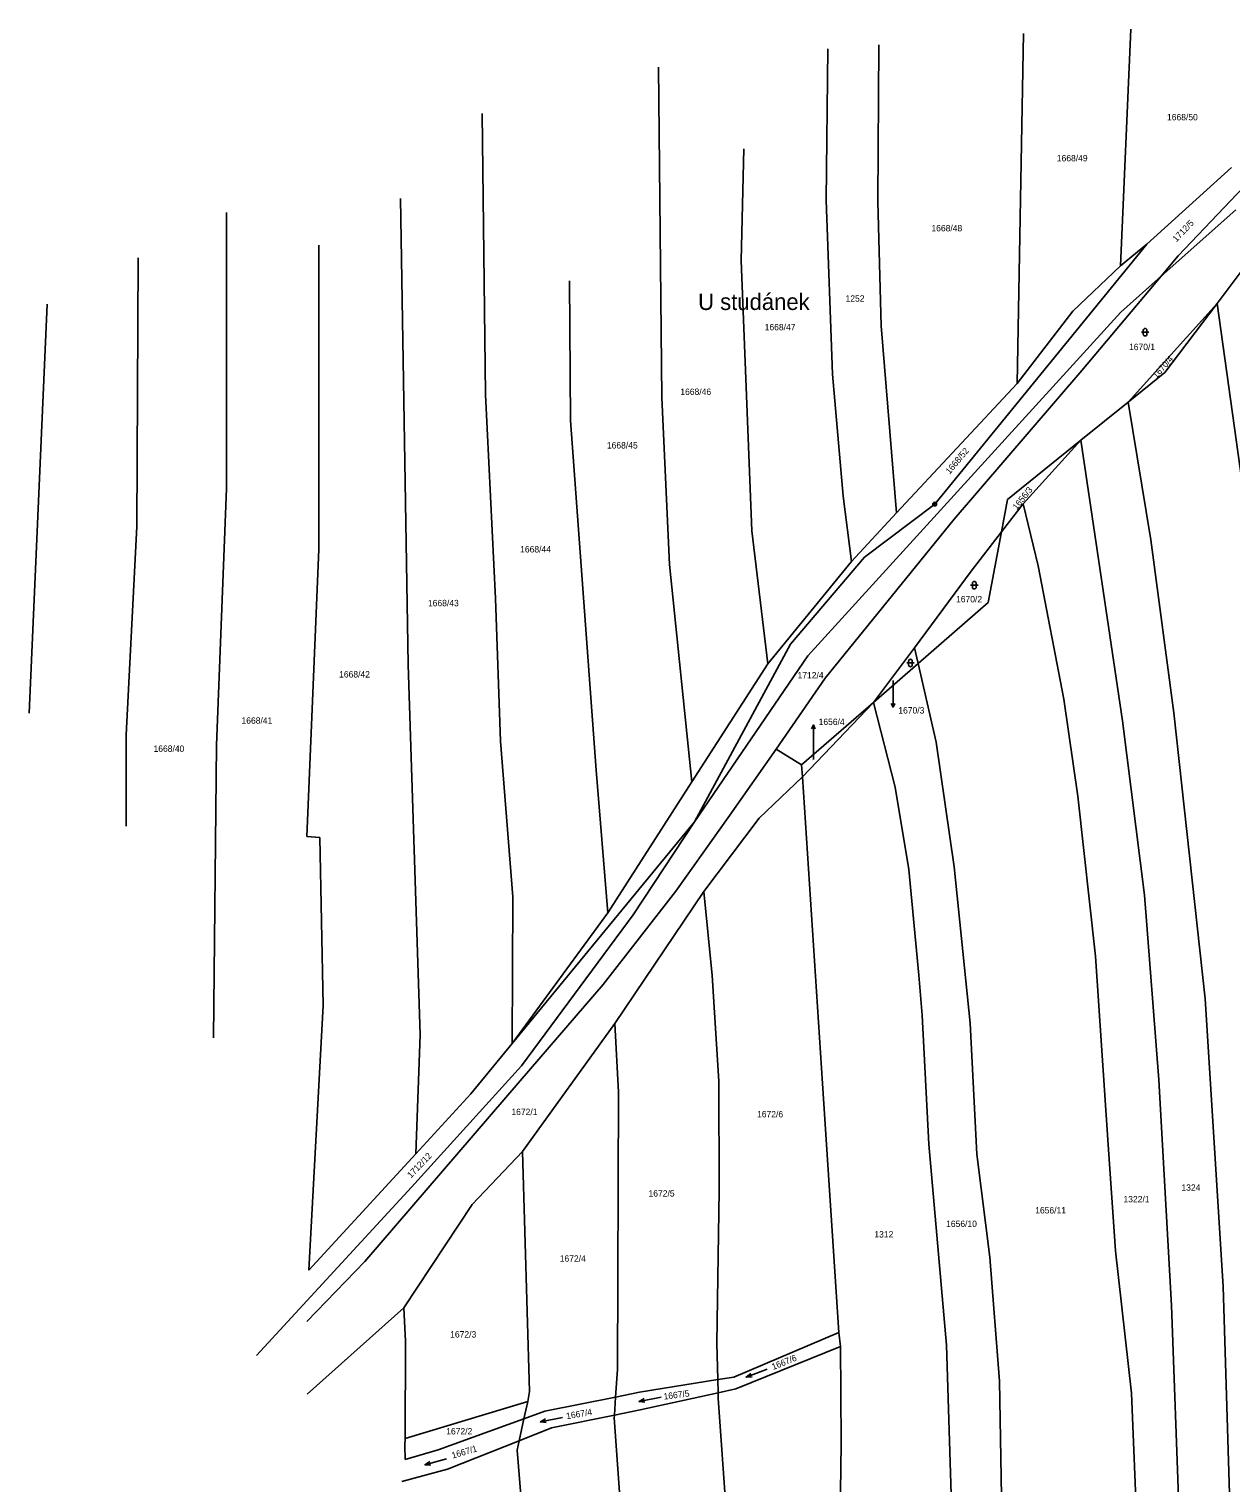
# Model space of a CAD drawing. Extents: x -763296 to -761805, y -1153670 to -1152034.
# Drawn here: x -763295.5 to -762975, y -1152752.7 to -1152364.9 of the extents above; entities that cross this region are included whole.
import ezdxf

# ---------------------------------------------------------------- set-up
doc = ezdxf.new("R2010")
doc.units = 0
for name, color, linetype in [('Vrstva 1', 7, 'Continuous'), ('Vrstva 15', 7, 'Continuous'), ('Vrstva 16', 7, 'Continuous'), ('Vrstva 18', 7, 'Continuous'), ('Vrstva 24', 7, 'Continuous'), ('Vrstva 25', 7, 'Continuous'), ('Vrstva 6', 7, 'Continuous')]:
    doc.layers.add(name, color=color, linetype=linetype)

msp = doc.modelspace()

# ---------------------------------------------------------------- linework, layer by layer
at = {"layer": 'Vrstva 1'}
for p, q in [((-762989.06, -1152425.44), (-762962.59, -1152397.59)), ((-762974.84, -1152401.85), (-762997.4, -1152422.3)), ((-762997.4, -1152422.3), (-763053.99, -1152491.63)), ((-762978.68, -1152438.1), (-762968.78, -1152424.96)), ((-762993.56, -1152430.81), (-762989.06, -1152425.44)), ((-763014.7, -1152456.04), (-762993.56, -1152430.81)), ((-762992.57, -1152456.53), (-762978.68, -1152438.1)), ((-763048.79, -1152495.66), (-763014.7, -1152456.04)), ((-763002.38, -1152464.44), (-762992.57, -1152456.53)), ((-763015, -1152474.6), (-763002.38, -1152464.44)), ((-763034.6, -1152490.4), (-763015, -1152474.6)), ((-763036.21, -1152499.07), (-763034.6, -1152490.4)), ((-763053.99, -1152491.63), (-763072.74, -1152505.77)), ((-763083.23, -1152538.1), (-763048.79, -1152495.66)), ((-763039.69, -1152517.84), (-763036.21, -1152499.07)), ((-763072.74, -1152505.77), (-763092.4, -1152529.01)), ((-763058.42, -1152534.15), (-763039.69, -1152517.84)), ((-763092.4, -1152529.01), (-763118.09, -1152576.34)), ((-763070.34, -1152544.53), (-763058.42, -1152534.15)), ((-763096.23, -1152556.97), (-763083.23, -1152538.1)), ((-763089.48, -1152561.2), (-763070.34, -1152544.53)), ((-763108.59, -1152574.57), (-763096.23, -1152556.97)), ((-763096.23, -1152556.97), (-763089.48, -1152561.2)), ((-763089.48, -1152561.2), (-763089.27, -1152564.37)), ((-763089.27, -1152564.37), (-763083.91, -1152646.15)), ((-763118.09, -1152576.34), (-763166.68, -1152635.49)), ((-763123, -1152594.92), (-763108.59, -1152574.57)), ((-763142.38, -1152619.81), (-763123, -1152594.92)), ((-763164.58, -1152645.44), (-763142.38, -1152619.81)), ((-763166.68, -1152635.49), (-763177.74, -1152648.96)), ((-763206.02, -1152693.64), (-763164.58, -1152645.44)), ((-763083.91, -1152646.15), (-763079.55, -1152712.57)), ((-763177.74, -1152648.96), (-763192.41, -1152664.95)), ((-763192.41, -1152664.95), (-763220.87, -1152695.98)), ((-763221.49, -1152709.63), (-763206.02, -1152693.64)), ((-763107.58, -1152724.48), (-763079.55, -1152712.57)), ((-763079.55, -1152712.57), (-763079.07, -1152716.28)), ((-763079.07, -1152716.28), (-763107.05, -1152727.6)), ((-763132.7, -1152728.51), (-763111.84, -1152725.16)), ((-763111.84, -1152725.16), (-763107.58, -1152724.48)), ((-763107.05, -1152727.6), (-763111.76, -1152728.64)), ((-763157.95, -1152733.58), (-763139.1, -1152729.8)), ((-763139.1, -1152729.8), (-763132.7, -1152728.51)), ((-763111.76, -1152728.64), (-763132.54, -1152733.23)), ((-763163.53, -1152735.6), (-763157.95, -1152733.58)), ((-763139.43, -1152734.62), (-763156.2, -1152738.01)), ((-763132.54, -1152733.23), (-763139.43, -1152734.62)), ((-763186.46, -1152743.92), (-763163.53, -1152735.6)), ((-763156.2, -1152738.01), (-763164.82, -1152741.44)), ((-763164.82, -1152741.44), (-763183.89, -1152749.01)), ((-763195.26, -1152746.46), (-763186.46, -1152743.92)), ((-763183.89, -1152749.01), (-763196.08, -1152752.36))]:
    msp.add_line(p, q, dxfattribs=at)
at = {"layer": 'Vrstva 16'}
for p, q in [((-763065.09, -1152538.71), (-763065.09, -1152542.8)), ((-763065.089, -1152545.8), (-763065.09, -1152542.8)), ((-763086.34, -1152550.55), (-763086.34, -1152553.55)), ((-763086.34, -1152559.8), (-763086.34, -1152553.55))]:
    msp.add_line(p, q, dxfattribs=at)
for points in [[(-763064.589, -1152544.8), (-763065.089, -1152545.8), (-763065.589, -1152544.8)], [(-763086.84, -1152551.55), (-763086.34, -1152550.55), (-763085.84, -1152551.55)]]:
    msp.add_lwpolyline(points, dxfattribs=at)
at = {"layer": 'Vrstva 24'}
for radius in [0.5, 0.1]:
    msp.add_circle((-763053.99, -1152491.63), radius, dxfattribs=at)
at = {"layer": 'Vrstva 25'}
for p, q in [((-762998.87, -1152445.8), (-762996.87, -1152445.8)), ((-762998.37, -1152446.3), (-762998.37, -1152445.3)), ((-762997.37, -1152445.3), (-762997.37, -1152446.3)), ((-763044.42, -1152513.28), (-763042.42, -1152513.28)), ((-763043.92, -1152513.78), (-763043.92, -1152512.78)), ((-763042.92, -1152512.78), (-763042.92, -1152513.78)), ((-763060.96, -1152534.52), (-763060.96, -1152533.52)), ((-763059.96, -1152533.52), (-763059.96, -1152534.52)), ((-763061.46, -1152534.02), (-763059.46, -1152534.02))]:
    msp.add_line(p, q, dxfattribs=at)
for points in [[(-763098.655, -1152722.402), (-763104.285, -1152724.478), (-763102.704, -1152724.428)], [(-763104.285, -1152724.478), (-763103.05, -1152723.49)], [(-763126.959, -1152729.819), (-763132.841, -1152731.001), (-763131.272, -1152731.196)], [(-763132.841, -1152731.001), (-763131.469, -1152730.215)], [(-763153.259, -1152735.239), (-763159.141, -1152736.421), (-763157.572, -1152736.616)], [(-763159.141, -1152736.421), (-763157.769, -1152735.635)], [(-763184.181, -1152746.25), (-763189.959, -1152747.87), (-763188.379, -1152747.946)], [(-763189.959, -1152747.87), (-763188.649, -1152746.984)]]:
    msp.add_lwpolyline(points, dxfattribs=at)
for centre, start, end in [((-762997.87, -1152445.3), 0, 180), ((-762997.87, -1152446.3), 180, 0), ((-763043.42, -1152512.78), 0, 180), ((-763043.42, -1152513.78), 180, 0), ((-763060.46, -1152533.52), 0, 180), ((-763060.46, -1152534.52), 180, 0)]:
    msp.add_arc(centre, 0.5, start, end, dxfattribs=at)
at = {"layer": 'Vrstva 6'}
for p, q in [((-763032.02, -1152459.44), (-763030.34, -1152366.1)), ((-763004.46, -1152428.13), (-763001.67, -1152364.94)), ((-763082.93, -1152410.61), (-763082.53, -1152370.23)), ((-763069.14, -1152410.96), (-763068.92, -1152369.16)), ((-763126.75, -1152463.22), (-763127.66, -1152375.1)), ((-763174.64, -1152387.43), (-763173.8, -1152462.4)), ((-763105.6, -1152426.7), (-763104.85, -1152396.86)), ((-763194.43, -1152534.44), (-763196.49, -1152410.13)), ((-763081.25, -1152456.97), (-763082.93, -1152410.61)), ((-763068.27, -1152444.11), (-763069.14, -1152410.96)), ((-762993.56, -1152430.81), (-762973.69, -1152413.15)), ((-763242.83, -1152487.51), (-763242.88, -1152413.84)), ((-763218.24, -1152503.78), (-763218.26, -1152422.55)), ((-763004.46, -1152428.13), (-762997.4, -1152422.3)), ((-763266.75, -1152497.64), (-763266.46, -1152425.91)), ((-763102.74, -1152498.8), (-763105.6, -1152426.7)), ((-763017.16, -1152440.17), (-763004.46, -1152428.13)), ((-763151.12, -1152469.34), (-763151.39, -1152432.11)), ((-763004.37, -1152440.42), (-762993.56, -1152430.81)), ((-763295.53, -1152547.37), (-763290.69, -1152438.31)), ((-763087.78, -1152532.12), (-763004.37, -1152440.42)), ((-763032.02, -1152459.44), (-763017.16, -1152440.17)), ((-763002.38, -1152464.44), (-762978.68, -1152438.1)), ((-762966.34, -1152526.12), (-762978.68, -1152438.1)), ((-763064.16, -1152493.93), (-763068.27, -1152444.11)), ((-763078.36, -1152489.54), (-763081.25, -1152456.97)), ((-763064.16, -1152493.93), (-763032.02, -1152459.44)), ((-763173.8, -1152462.4), (-763171.13, -1152516.86)), ((-763126.75, -1152463.22), (-763124.75, -1152507.74)), ((-762996.3, -1152501.19), (-763002.38, -1152464.44)), ((-763144.28, -1152562.61), (-763151.12, -1152469.34)), ((-763030.42, -1152491.54), (-763015, -1152474.6)), ((-763003.86, -1152549.48), (-763015, -1152474.6)), ((-763245.55, -1152555.9), (-763242.83, -1152487.51)), ((-763076.18, -1152506.95), (-763078.36, -1152489.54)), ((-763076.18, -1152506.95), (-763064.16, -1152493.93)), ((-763036.21, -1152499.07), (-763030.42, -1152491.54)), ((-763026.37, -1152508.13), (-763030.42, -1152491.54)), ((-763269.64, -1152553.2), (-763266.75, -1152497.64)), ((-763098.51, -1152534.23), (-763102.74, -1152498.8)), ((-763044.24, -1152509.56), (-763036.21, -1152499.07)), ((-762990.17, -1152547.32), (-762996.3, -1152501.19)), ((-763221.42, -1152580.31), (-763218.24, -1152503.78)), ((-763124.75, -1152507.74), (-763118.73, -1152565.68)), ((-763098.51, -1152534.23), (-763076.18, -1152506.95)), ((-763059.35, -1152529.99), (-763044.24, -1152509.56)), ((-763019.5, -1152543.67), (-763026.37, -1152508.13)), ((-763171.13, -1152516.86), (-763169.77, -1152554.85)), ((-763070.34, -1152544.53), (-763059.35, -1152529.99)), ((-763058.42, -1152534.15), (-763059.35, -1152529.99)), ((-763118.09, -1152576.34), (-763087.78, -1152532.12)), ((-763191.19, -1152633.21), (-763194.43, -1152534.44)), ((-763118.73, -1152565.68), (-763098.51, -1152534.23)), ((-763053.57, -1152555.15), (-763058.42, -1152534.15)), ((-763070.34, -1152544.53), (-763089.27, -1152564.37)), ((-763064.54, -1152567.18), (-763070.34, -1152544.53)), ((-763015.83, -1152569.55), (-763019.5, -1152543.67)), ((-762981.82, -1152623.56), (-762990.17, -1152547.32)), ((-763269.64, -1152577.54), (-763269.64, -1152553.2)), ((-762998.06, -1152595.97), (-763003.86, -1152549.48)), ((-763246.31, -1152634.04), (-763245.55, -1152555.9)), ((-763169.77, -1152554.85), (-763166.49, -1152596.43)), ((-763048.8, -1152588.35), (-763053.57, -1152555.15)), ((-763141.19, -1152600.66), (-763144.28, -1152562.61)), ((-763100.79, -1152575.38), (-763089.27, -1152564.37)), ((-763141.19, -1152600.66), (-763118.73, -1152565.68)), ((-763060.89, -1152589.11), (-763064.54, -1152567.18)), ((-763011.11, -1152612.2), (-763015.83, -1152569.55)), ((-763134.42, -1152601.17), (-763118.09, -1152576.34)), ((-763100.79, -1152575.38), (-763115.53, -1152595)), ((-763217.97, -1152580.6), (-763221.42, -1152580.31)), ((-763217.06, -1152625.38), (-763217.97, -1152580.6)), ((-763058.24, -1152617.32), (-763060.89, -1152589.11)), ((-763044.53, -1152630.06), (-763048.8, -1152588.35)), ((-763139.32, -1152630.21), (-763115.53, -1152595)), ((-763115.53, -1152595), (-763113.3, -1152617.36)), ((-763166.49, -1152596.43), (-763166.68, -1152635.49)), ((-762994.2, -1152645.19), (-762998.06, -1152595.97)), ((-763166.68, -1152635.49), (-763141.19, -1152600.66)), ((-763164.21, -1152641.44), (-763134.42, -1152601.17)), ((-763007.84, -1152661.17), (-763011.11, -1152612.2)), ((-763113.3, -1152617.36), (-763111.6, -1152645.57)), ((-763057.33, -1152627.93), (-763058.24, -1152617.32)), ((-763217.06, -1152625.38), (-763220.87, -1152695.98)), ((-762977.04, -1152700.29), (-762981.82, -1152623.56)), ((-763139.32, -1152630.21), (-763163.94, -1152664.29)), ((-763138.36, -1152648.48), (-763139.32, -1152630.21)), ((-763055.51, -1152662.37), (-763057.33, -1152627.93)), ((-763042.74, -1152665.04), (-763044.53, -1152630.06)), ((-763192.41, -1152664.95), (-763191.19, -1152633.21)), ((-763193.54, -1152673.82), (-763164.21, -1152641.44)), ((-763111.5, -1152674.68), (-763111.6, -1152645.57)), ((-762990.82, -1152705.37), (-762994.2, -1152645.19)), ((-763138.58, -1152722.49), (-763138.36, -1152648.48)), ((-763007.84, -1152661.17), (-763005.79, -1152690.79)), ((-763163.94, -1152664.29), (-763177.33, -1152678.41)), ((-763162.05, -1152728.33), (-763163.94, -1152664.29)), ((-763050.86, -1152715.94), (-763055.51, -1152662.37)), ((-763039.32, -1152692.5), (-763042.74, -1152665.04)), ((-763234.83, -1152718.68), (-763193.54, -1152673.82)), ((-763112.05, -1152715.47), (-763111.5, -1152674.68)), ((-763177.33, -1152678.41), (-763195.57, -1152706.03)), ((-763036.66, -1152725.61), (-763039.32, -1152692.5)), ((-763005.79, -1152690.79), (-763001.47, -1152728.76)), ((-762975.11, -1152762.91), (-762977.04, -1152700.29)), ((-763195.57, -1152706.03), (-763221.37, -1152729.03)), ((-763195.16, -1152715.02), (-763195.57, -1152706.03)), ((-762988.65, -1152764.58), (-762990.82, -1152705.37)), ((-763195.23, -1152740.82), (-763195.16, -1152715.02)), ((-763112.05, -1152715.47), (-763111.84, -1152725.16)), ((-763048.38, -1152793.73), (-763050.86, -1152715.94)), ((-763079.06, -1152728.59), (-763079.07, -1152716.28)), ((-763139.1, -1152729.8), (-763138.58, -1152722.49)), ((-763111.84, -1152725.16), (-763111.76, -1152728.64)), ((-763036.03, -1152765.53), (-763036.66, -1152725.61)), ((-763195.23, -1152740.82), (-763162.53, -1152730.98)), ((-763162.53, -1152730.98), (-763163.53, -1152735.6)), ((-763162.53, -1152730.98), (-763162.05, -1152728.33)), ((-763139.43, -1152734.62), (-763139.1, -1152729.8)), ((-763111.76, -1152728.64), (-763111.73, -1152730.09)), ((-763104.2, -1152836.3), (-763111.73, -1152730.09)), ((-763079.06, -1152728.59), (-763078.89, -1152742.27)), ((-763001.47, -1152728.76), (-762999.98, -1152764.63)), ((-763139.48, -1152735.36), (-763139.43, -1152734.62)), ((-763135.14, -1152794.51), (-763139.48, -1152735.36)), ((-763163.53, -1152735.6), (-763164.82, -1152741.44)), ((-763195.27, -1152742.73), (-763195.23, -1152740.82)), ((-763195.26, -1152746.46), (-763195.27, -1152742.73)), ((-763164.82, -1152741.44), (-763165.36, -1152743.95)), ((-763078.89, -1152742.27), (-763079.9, -1152805.54)), ((-763162.09, -1152784.23), (-763165.36, -1152743.95))]:
    msp.add_line(p, q, dxfattribs=at)

# ---------------------------------------------------------------- texts
at = {"layer": 'Vrstva 15'}
msp.add_text('U studánek', height=4.4, dxfattribs=at).set_placement((-763117.092, -1152439.87))
at = {"layer": 'Vrstva 16'}
for s, p in [('1656/4', (-763084.947, -1152550.55)), ('1670/3', (-763063.697, -1152547.5))]:
    msp.add_text(s, height=1.7, dxfattribs=at).set_placement(p)
at = {"layer": 'Vrstva 18'}
for s, p in [('1668/50', (-762992.024, -1152389.28)), ('1668/49', (-763021.41, -1152400.22)), ('1668/48', (-763054.851, -1152418.89)), ('1252', (-763077.76, -1152437.64)), ('1668/47', (-763099.33, -1152445.29)), ('1670/1', (-763002.153, -1152450.57)), ('1668/46', (-763121.83, -1152462.52)), ('1668/45', (-763141.417, -1152476.81)), ('1668/44', (-763164.55, -1152504.54)), ('1668/43', (-763189.147, -1152518.88)), ('1670/2', (-763048.295, -1152517.85)), ('1668/42', (-763212.834, -1152537.89)), ('1712/4', (-763090.57, -1152538.14)), ('1668/41', (-763238.872, -1152550.21)), ('1668/40', (-763262.337, -1152557.72)), ('1672/1', (-763166.89, -1152654.6)), ('1672/6', (-763101.368, -1152655.21)), ('1324', (-762988.176, -1152674.79)), ('1672/5', (-763130.315, -1152676.33)), ('1322/1', (-763003.631, -1152677.87)), ('1656/11', (-763027.175, -1152680.84)), ('1656/10', (-763050.939, -1152684.44)), ('1312', (-763070.078, -1152687.25)), ('1672/4', (-763153.998, -1152693.72)), ('1672/3', (-763183.215, -1152713.93)), ('1672/2', (-763184.272, -1152739.78))]:
    msp.add_text(s, height=1.7, dxfattribs=at).set_placement(p)
for s, height, rotation, p in [('1712/5', 1.7, 46.29499, (-762989.503, -1152421.845)), ('1670/4', 1.7, 48.70141, (-762994.792, -1152458.256)), ('1668/52', 1.7, 50.1911, (-763049.972, -1152483.792)), ('1656/3', 1.7, 51.45161, (-763032.076, -1152493.307)), ('1670/3', 0.1, 39.82057, (-763065.264, -1152538.855)), ('1656/4', 0.1, 45.43555, (-763086.498, -1152559.96)), ('1712/12', 1.7, 46.29499, (-763193.657, -1152671.541)), ('1667/6', 1.7, 21.94428, (-763097.054, -1152722.605)), ('1667/5', 1.7, 7.16197, (-763126.192, -1152730.501)), ('1667/4', 1.7, 9.68299, (-763152.121, -1152735.738)), ('1667/1', 1.7, 16.50118, (-763182.537, -1152746.232))]:
    msp.add_text(s, height=height, rotation=rotation, dxfattribs=at).set_placement(p)

doc.saveas('drawing.dxf')
